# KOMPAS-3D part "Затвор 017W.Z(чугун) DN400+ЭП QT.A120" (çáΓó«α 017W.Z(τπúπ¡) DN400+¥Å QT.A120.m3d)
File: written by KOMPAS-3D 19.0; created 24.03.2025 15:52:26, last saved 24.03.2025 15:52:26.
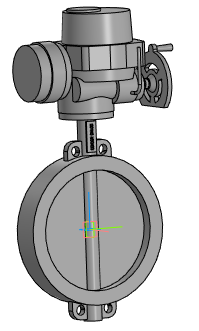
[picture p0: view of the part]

Document properties: Полное имя файла: Затвор 017W.Z(чугун) DN400+ЭП QT.A120.a3d

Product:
- Part/product: Затвор 017W.Z(чугун) DN400+ЭП QT.A120
    Масса: 225.618

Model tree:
1. Операция без истории:1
